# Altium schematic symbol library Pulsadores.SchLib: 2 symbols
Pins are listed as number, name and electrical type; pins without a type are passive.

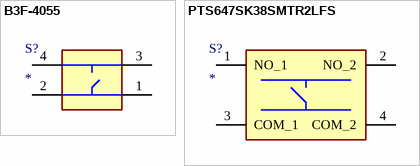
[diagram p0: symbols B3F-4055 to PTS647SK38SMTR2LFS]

## B3F-4055
designator S?
Switch; Manufacturer_Name: Omron Electronics; Manufacturer_Part_Number: B3F-4055
footprint B3F-4055
pins: 1, 2, 3, 4

## PTS647SK38SMTR2LFS
designator S?
Switch; Manufacturer_Name: C & K COMPONENTS; Manufacturer_Part_Number: PTS647SK38SMTR2LFS
footprint PTS647SK38SMTR2LFS
pins: 1 NO_1, 2 NO_2, 3 COM_1, 4 COM_2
